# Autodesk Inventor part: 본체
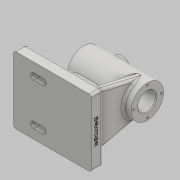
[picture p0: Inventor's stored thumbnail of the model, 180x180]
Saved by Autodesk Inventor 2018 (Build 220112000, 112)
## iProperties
Created: 2022-06
Part Number: 본체
Material: 일반
Document SubType Name: Modeling
Designer: home
Density: 1 g/cm^3
Appearance: 기본값
Author: home
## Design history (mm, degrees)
sketch "스케치1"
  geometry: L1 (50, -43)-(-50, -43); L2 (-50, -43)-(-50, 43); L3 (-50, 43)-(50, 43); L4 (50, 43)-(50, -43); L5 (50, -43)-(-50, 43); 2 further points
  constraints: 10 end point, 2 parallel, 1 coincident, 1 horizontal, 1 midpoint, 1 perpendicular
  dimensions: "d0" = 100 distance of L1.start L1.end; "d1" = 86 distance of L1.end L2.end
extrude "돌출1" new body sketch "스케치1" distance "d2" = 15; taper "d3" = 0 deg
sketch "스케치2"
  geometry: L1 (-49, 72)-(53, 72); L2 (-50, 0)-(50, 0) reference; L3 (-32, 86.5)-(30, 86.5); L4 (30, 86.5)-(30, 83.5); L5 (30, 83.5)-(50, 83.5); L6 (50, 83.5)-(50, 93); L7 (50, 93)-(-32, 93); L8 (-32, 93)-(-32, 86.5); 2 further points
  constraints: 14 end point, 5 perpendicular, 2 horizontal, 1 vertical alignment
  dimensions: "d4" = 72 distance between parallel lines of L2 L1; "d5" = 82 distance of L6.end L7.end; "d6" = 42 diameter of L7 L1; "d7" = 23 diameter of L5 L1; "d8" = 29 diameter of L3 L1; "d9" = 62 distance of L3.start L3.end; "d15" = 3 distance from line of L1.end L6; "d16" = 99 distance from line of L1.start L6
revolve "회전1" sketch "스케치2" stored, may be unused: angle "d10" = 90 deg
node "작업 평면1"
sketch "스케치3"
  geometry: L1 (-50, -43)-(-50, 43) reference; L2 (-32, -21)-(-32, 21) reference; C1 r 11 at (-7, 0); 1 further point
  constraints: 1 centre point, 1 horizontal alignment
  dimensions: "d12" = 22 diameter of C1; "d14" = 25 distance from line of C1.centre L2
extrude "돌출2" join sketch "스케치3" stored distance "d17" = 15; taper "d18" = 0 deg
sketch "스케치4"
  geometry: C1 r 11 at (0, 0) reference; 1 further point
hole "구멍1" sketch "스케치4" at (0, 0) diameter "d19" = 4.917; stored, may be unused: countersink angle "d23" = 90 deg, drill point angle "d25" = 118 deg; dims "d20" = 12, "d21" = 14, "d22" = 4, "d24" = 17.1
sketch "스케치5"
  geometry: C1 r 11.5 at (0, 0) reference; 2 further points
  constraints: 1 vertical alignment
  dimensions: "d26" = 18 distance of point (0, 18) C1.centre
hole "구멍2" sketch "스케치5" at (0, 18) diameter "d27" = 2.459; stored, may be unused: countersink angle "d31" = 90 deg, drill point angle "d33" = 118 deg; dims "d28" = 8, "d29" = 10, "d30" = 4, "d32" = 10
sketch "스케치6"
  geometry: C1 r 11.5 at (0, 0) reference; 2 further points
  constraints: 1 vertical alignment
  dimensions: "d37" = 18 distance of point (0, 18) C1.centre
hole "구멍3" sketch "스케치6" at (0, 18) diameter "d38" = 2.459; stored, may be unused: countersink angle "d42" = 90 deg, drill point angle "d44" = 118 deg; dims "d39" = 8, "d40" = 10, "d41" = 4, "d43" = 10
node "작업 평면2"
sketch "스케치7"
  geometry: L1 (86, 15)-(0, 15) reference; L2 (8, 15)-(22.559, 76.814); L3 (63.441, 76.814)-(78, 15); L4 (0, 0)-(0, 15) reference; L5 (86, 0)-(86, 15) reference; L6 (8, 15)-(78, 15); A1 r 21 centre (43, 72) between (22.559, 76.814) and (63.441, 76.814) reference; 1 further point
  constraints: 6 end point, 2 point on circle, 2 point on line, 2 tangent, 1 collinear
  dimensions: "d49" = 8 distance from line of L4 L2.start; "d50" = 8 distance from line of L5 L3.end
feature "리브1" sketch "스케치7" dims "d51" = 1, "d52" = 10, "d53" = 0, "d54" = 0, "d55" = 1, "d56" = 1
sketch "스케치8"
  geometry: L1 (-21.897, 51)-(-35, 15); L2 (50, 15)-(-50, 15) reference; L3 (-50, 0)-(-50, 15) reference; L4 (-32, 51)-(50, 51) reference; 1 further point
  constraints: 2 end point, 2 point on line
  dimensions: "d57" = 70 deg angle of L2 L1; "d58" = 15 distance from line of L3 L1.end
feature "리브2" sketch "스케치8" dims "d59" = 1, "d60" = 10, "d61" = 0, "d62" = 0, "d63" = 1, "d64" = 1
sketch "스케치9"
  geometry: L1 (-24, 27)-(-12, 27); L2 (-24, 20)-(-12, 20); L3 (-12, 34)-(-24, 34); L4 (-50, -43)-(-50, 43) reference; L5 (-50, 43)-(50, 43) reference; A1 r 7 centre (-24, 27) between (-24, 34) and (-24, 20); A2 r 7 centre (-12, 27) between (-12, 20) and (-12, 34); 2 further points
  constraints: 8 end point, 4 point on circle, 4 tangent, 2 centre point, 1 horizontal, 1 midpoint, 1 parallel
  dimensions: "d65" = 12 distance of L1.start L1.end; "d66" = 26 distance from line of L4 L1.start; "d67" = 7 radius of A1; "d68" = 16 distance from line of L5 point (-18, 27)
extrude "돌출3" join sketch "스케치9" distance "d69" = 3; taper "d70" = 0 deg
sketch "스케치10"
  geometry: L1 (-24, 27)-(-12, 27); L2 (-24, 23)-(-12, 23); L3 (-12, 31)-(-24, 31); L4 (50, 43)-(-50, 43) reference; A1 r 7 centre (-24, 27) between (-24, 34) and (-24, 20) reference; A2 r 7 centre (-12, 27) between (-12, 20) and (-12, 34) reference; A3 r 4 centre (-24, 27) between (-24, 31) and (-24, 23); A4 r 4 centre (-12, 27) between (-12, 23) and (-12, 31); 3 further points
  constraints: 8 end point, 4 point on circle, 4 tangent, 2 centre point, 1 horizontal, 1 midpoint, 1 parallel
  dimensions: "d71" = 8 diameter of A4; "d74" = 16 distance between parallel lines of L1 L4 (derived)
extrude "돌출4" cut sketch "스케치10" extent not by distance; stored distance "d72" = 3; taper "d73" = 0 deg
sketch "스케치11"
  geometry: L1 (86, 0)-(0, 0) reference; 3 further points
  constraints: 1 midpoint, 1 vertical alignment, 1 other
  dimensions: "d75" = 6 distance from line of L1 point (43, 6)
feature "엠보싱1" sketch "스케치11" dims "d0" = 100, "d1" = 86, "d76" = 0.5, "d77" = 0
fillet "모깎기1" dims "d78" = 3
fillet "모깎기2" dims "d79" = 3
fillet "모깎기3" dims "d80" = 3
fillet "모깎기4" dims "d81" = 3
chamfer "모따기1" distance "d82" = 1; stored, may be unused: second distance "d83" = 2, angle "d84" = 45 deg
fillet "모깎기5" dims "d85" = 3
fillet "모깎기6" dims "d86" = 3
fillet "모깎기7" dims "d87" = 1
node "솔리드1"
pattern_circular "원형 패턴1" dims angle "d35" = 360 deg
pattern_circular "원형 패턴2" dims angle "d46" = 360 deg
mirror "미러1"
node "투영된 루프1"
other parameters: "d11" = -96, "d48" = -15
